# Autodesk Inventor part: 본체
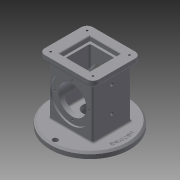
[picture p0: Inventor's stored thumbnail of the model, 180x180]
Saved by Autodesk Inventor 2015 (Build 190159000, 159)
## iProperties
Created: 2019-08
Part Number: 본체
Material: 일반
Document SubType Name: Modeling
Designer: CAD-08
Density: 1 g/cm^3
Appearance: 기본값
Author: CAD-08
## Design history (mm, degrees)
sketch "스케치1"
  geometry: C1 r 67.5 at (0, 0); 1 further point
  constraints: 1 centre point, 1 coincident
  dimensions: "d0" = 135 diameter of C1
extrude "돌출1" new body sketch "스케치1" distance "d1" = 10; taper "d2" = 0 deg
sketch "스케치2"
  geometry: L1 (-37, 33)-(37, 33); L2 (37, 33)-(37, -33); L3 (37, -33)-(-37, -33); L4 (-37, -33)-(-37, 33); L5 (-37, 33)-(37, -33); L6 (37, 33)-(-37, -33); C1 r 67.5 at (0, 0) reference
  constraints: 12 end point, 2 midpoint, 2 parallel, 1 horizontal, 1 perpendicular
  dimensions: "d3" = 66 distance of L1.end L2.end; "d4" = 74 distance of L1.start L1.end
extrude "돌출2" join sketch "스케치2" distance "d5" = 88; taper "d6" = 0 deg
sketch "스케치3"
  geometry: L1 (-46, 41)-(46, 41); L2 (46, 41)-(46, -41); L3 (46, -41)-(-46, -41); L4 (-46, -41)-(-46, 41); L5 (-46, 41)-(46, -41); L6 (46, 41)-(-46, -41); 1 further point
  constraints: 12 end point, 2 midpoint, 2 parallel, 1 horizontal, 1 perpendicular
  dimensions: "d7" = 92 distance of L2.end L3.end; "d8" = 82 distance of L1.end L2.end
extrude "돌출3" join sketch "스케치3" distance "d9" = 10; taper "d10" = 0 deg
chamfer "모따기1" distance "d11" = 3; stored, may be unused: second distance "d12" = 2, angle "d13" = 45 deg
sketch "스케치4"
  geometry: L1 (-26, 26)-(26, 26); L2 (26, 26)-(26, -26); L3 (26, -26)-(-26, -26); L4 (-26, -26)-(-26, 26); L5 (-26, 26)-(26, -26); L6 (26, 26)-(-26, -26); 1 further point
  constraints: 12 end point, 2 midpoint, 2 parallel, 1 horizontal, 1 perpendicular
  dimensions: "d16" = 52 distance of L2.end L3.end; "d17" = 52 distance of L1.end L2.end
extrude "돌출4" cut sketch "스케치4" distance "d18" = 8; taper "d19" = 0 deg
sketch "스케치5"
  geometry: L1 (-22, 22)-(22, 22); L2 (22, 22)-(22, -22); L3 (22, -22)-(-22, -22); L4 (-22, -22)-(-22, 22); L5 (-22, 22)-(22, -22); L6 (22, 22)-(-22, -22); 1 further point
  constraints: 12 end point, 2 midpoint, 2 parallel, 1 horizontal, 1 perpendicular
  dimensions: "d20" = 44 distance of L2.end L3.end; "d21" = 44 distance of L3.end L1.start
extrude "돌출5" cut sketch "스케치5" distance "d22" = 74; taper "d23" = 0 deg
sketch "스케치6"
  geometry: C1 r 67.5 at (0, 0) reference
hole "구멍1" sketch "스케치6" at (0, 0) diameter "d24" = 25; stored, may be unused: countersink angle "d28" = 90 deg, drill point angle "d30" = 0 deg; dims "d25" = 6, "d26" = 50, "d27" = 18, "d29" = 50
fillet "모깎기3" dims "d31" = 10
fillet "모깎기4" dims "d32" = 3
fillet "모깎기5" dims "d33" = 3
sketch "스케치9"
  geometry: A1 r 10 centre (36, 31) between (46, 31) and (36, 41) reference; A2 r 10 centre (-36, 31) between (-36, 41) and (-46, 31) reference; A3 r 10 centre (-36, -31) between (-46, -31) and (-36, -41) reference; A4 r 10 centre (36, -31) between (36, -41) and (46, -31) reference; 1 further point
hole "구멍4" sketch "스케치9" at (36, -31), (36, 31), (-36, 31), (-36, -31) diameter "d53" = 3.242; stored, may be unused: countersink angle "d57" = 90 deg, drill point angle "d59" = 118 deg; dims "d54" = 4, "d55" = 70, "d56" = 3, "d58" = 6
fillet "모깎기6" dims "d69" = 3
sketch "스케치11"
  geometry: C1 r 64.5 at (0, 0) reference; C2 r 59 at (0, 0)
  constraints: 1 centre point, 1 coincident, 1 other
  dimensions: "d70" = 118 diameter of C2
feature "엠보싱1" sketch "스케치11" dims "d2" = 0, "d10" = 0, "d71" = 0.5, "d72" = 0
chamfer "모따기2" distance "d73" = 1; stored, may be unused: second distance "d74" = 2, angle "d75" = 45 deg
fillet "모깎기7" dims "d76" = 3
fillet "모깎기9" dims "d78" = 3
fillet "모깎기10" dims "d79" = 3
sketch "스케치12"
  geometry: C1 r 64.5 at (0, 0) reference; A1 r 59 centre (0, 0) between (-59, 0) and (0, 59); 1 further point
  constraints: 3 point on circle, 2 vertical alignment, 1 centre point, 1 coincident, 1 horizontal alignment
  dimensions: "d80" = 118 diameter of A1
hole "구멍6" sketch "스케치12" at (-59, 0), (0, 59), (0, -59) diameter "d81" = 9; stored, may be unused: countersink angle "d85" = 90 deg, drill point angle "d87" = 0 deg; dims "d82" = 12, "d83" = 70, "d84" = 3, "d86" = 30
fillet "모깎기11" dims "d88" = 3
sketch "스케치13"
  geometry: L1 (-33.5, -95)-(101.5, -95) reference; 2 further points
  constraints: 1 vertical alignment
  dimensions: "d89" = 54 distance from line of L1 point (34, -41)
hole "구멍7" sketch "스케치13" at (34, -41) diameter "d90" = 48; stored, may be unused: countersink angle "d94" = 90 deg, drill point angle "d96" = 0 deg; dims "d91" = 12, "d92" = 70, "d93" = 3, "d95" = 30
sketch "스케치14"
  geometry: L1 (95, -37.5)-(95, 97.5) reference; 4 further points
  constraints: 2 horizontal alignment, 1 midpoint
  dimensions: "d97" = 37 distance from line of L1 point (58, 30); "d98" = 43 distance of point (58, 30) point (15, 30)
hole "구멍8" sketch "스케치14" at (15, 30), (58, 30) diameter "d99" = 4.917; stored, may be unused: countersink angle "d103" = 90 deg, drill point angle "d105" = 0 deg; dims "d100" = 12, "d101" = 70, "d102" = 3, "d104" = 30
sketch "스케치15"
  geometry: C1 r 35 at (0, 0) reference; 2 further points
  constraints: 1 vertical alignment
  dimensions: "d106" = 29 distance of C1.centre point (0, 29)
hole "구멍9" sketch "스케치15" at (0, 29) diameter "d107" = 3.242; stored, may be unused: countersink angle "d111" = 90 deg, drill point angle "d113" = 118 deg; dims "d108" = 4, "d109" = 70, "d110" = 3, "d112" = 6
node "솔리드1"
mirror "대칭3"
pattern_circular "원형 패턴2" dims angle "d115" = 360 deg
mirror "대칭4"
